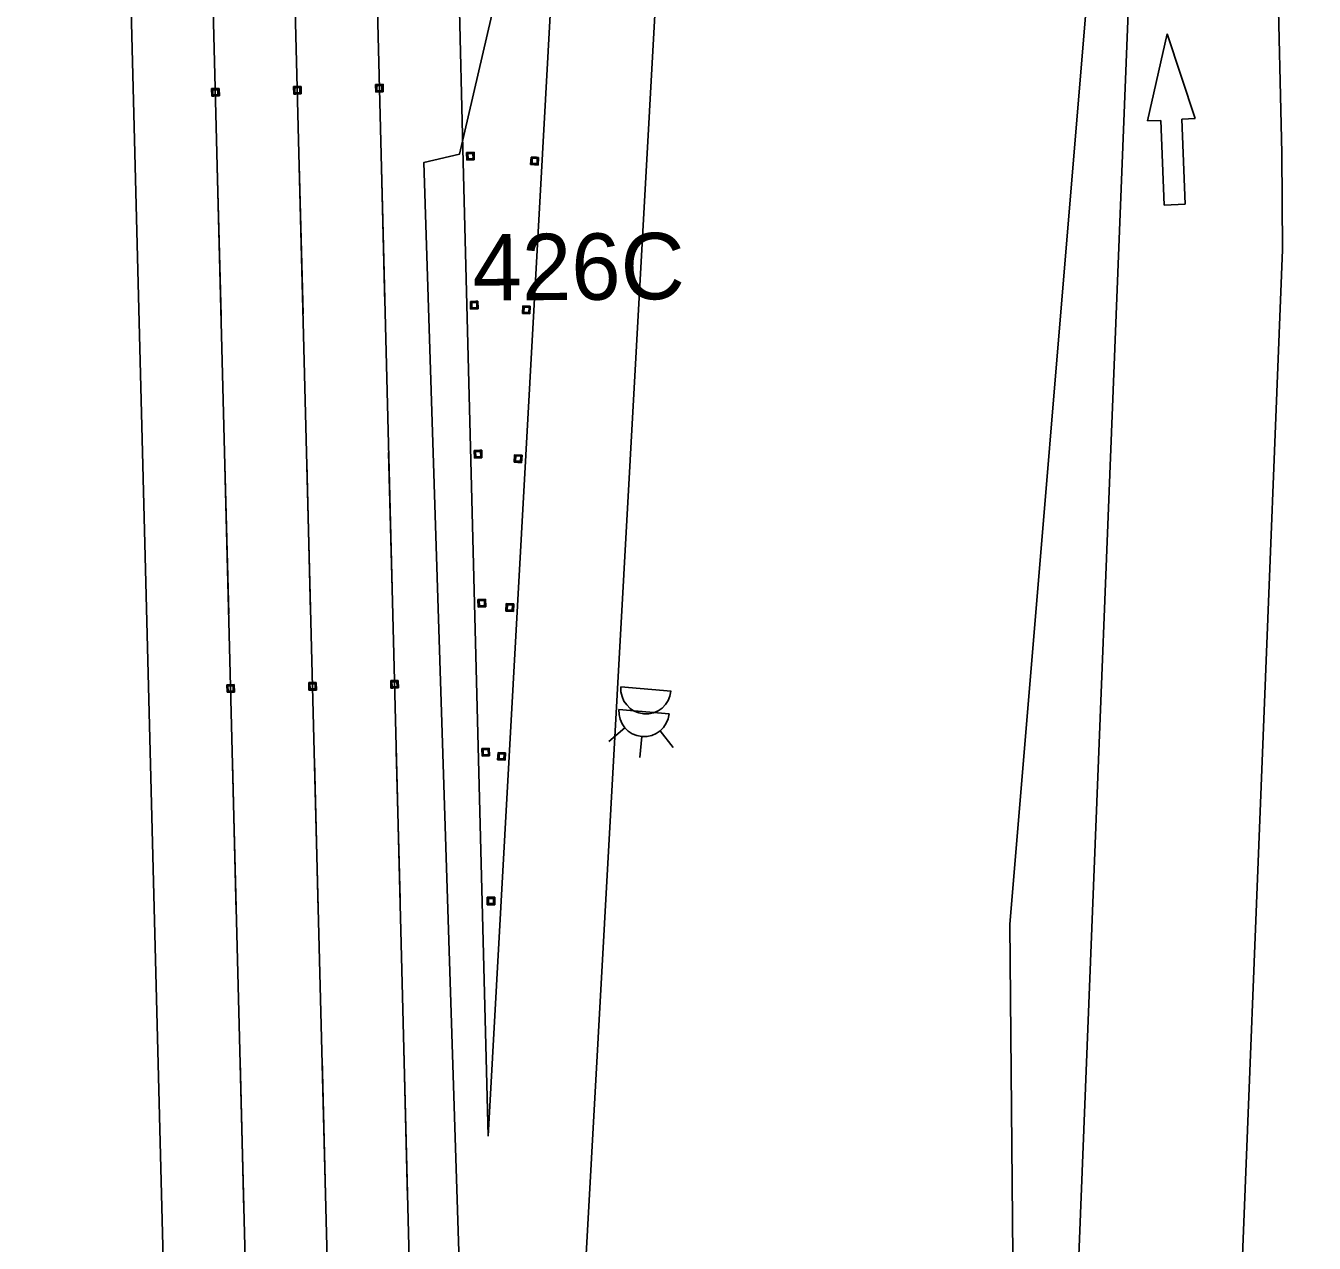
# Model space of a CAD drawing. Extents: x 2471014 to 2497726, y 6959577 to 6980268.
# Drawn here: x 2488544.1 to 2488716.9, y 6961658.6 to 6961822 of the extents above; entities that cross this region are included whole.
import ezdxf

# ---------------------------------------------------------------- set-up
doc = ezdxf.new("R2010")
doc.units = 0
for name, color, linetype in [('13', 7, 'Continuous'), ('18', 7, 'Continuous'), ('23', 7, 'Continuous'), ('25', 7, 'Continuous'), ('ALIGN_ML_IH35_NB_SB', 7, 'Continuous'), ('C-COMM-IDEN', 7, 'Continuous'), ('PMK_Pav_Mark_Wht_Number', 7, 'Continuous'), ('RDWY_PAVE_XSTREET_FOC', 7, 'Continuous'), ('V7_25', 7, 'Continuous'), ('V7_50', 7, 'Continuous')]:
    doc.layers.add(name, color=color, linetype=linetype)

msp = doc.modelspace()

# ---------------------------------------------------------------- linework, layer by layer
at = {"layer": '13'}
for p, q in [((2488544.08, 6962379.72), (2488575.08, 6961163.02)), ((2488613.41, 6961804.76), (2488630.42, 6962111.35)), ((2488683.27, 6961604.88), (2488692.01, 6961824.92))]:
    msp.add_line(p, q, dxfattribs=at)
at = {"layer": '18'}
for p, q in [((2488588.07, 6962380.84), (2488602.73, 6961805.44)), ((2488616.31, 6961604.28), (2488644.4, 6962110.57)), ((2488707.08, 6961650.46), (2488712.7, 6961791.89))]:
    msp.add_line(p, q, dxfattribs=at)
msp.add_lwpolyline([(2488712.7, 6961791.89), (2488712.61, 6961804.88), (2488712.01, 6961829.87), (2488710.72, 6961854.85), (2488708.49, 6961879.81), (2488698.22, 6961952.71)], dxfattribs=at)
at = {"layer": '23'}
for p, q in [((2488570.03, 6961813.55), (2488569.01, 6961813.53)), ((2488569.04, 6961812.51), (2488569.01, 6961813.53)), ((2488569.01, 6961813.53), (2488569.18, 6961813.36)), ((2488569.19, 6961812.68), (2488569.04, 6961812.51)), ((2488569.18, 6961813.36), (2488569.32, 6961813.36)), ((2488569.87, 6961812.7), (2488569.19, 6961812.68)), ((2488569.32, 6961813.36), (2488569.85, 6961813.38)), ((2488569.85, 6961813.38), (2488570.03, 6961813.55)), ((2488570.05, 6961812.54), (2488569.87, 6961812.7)), ((2488570.03, 6961813.55), (2488570.05, 6961812.54)), ((2488581.02, 6961813.83), (2488580.01, 6961813.81)), ((2488580.04, 6961812.79), (2488580.01, 6961813.81)), ((2488580.01, 6961813.81), (2488580.17, 6961813.64)), ((2488580.19, 6961812.96), (2488580.04, 6961812.79)), ((2488580.04, 6961812.79), (2488580.3, 6961812.8)), ((2488580.17, 6961813.64), (2488580.31, 6961813.64)), ((2488580.87, 6961812.98), (2488580.19, 6961812.96)), ((2488580.3, 6961812.8), (2488581.05, 6961812.82)), ((2488580.31, 6961813.64), (2488580.85, 6961813.66)), ((2488580.85, 6961813.66), (2488581.02, 6961813.83)), ((2488581.05, 6961812.82), (2488580.87, 6961812.98)), ((2488581.02, 6961813.83), (2488581.05, 6961812.82)), ((2488592.02, 6961814.11), (2488591.01, 6961814.09)), ((2488591.03, 6961813.07), (2488591.01, 6961814.09)), ((2488591.01, 6961814.09), (2488591.17, 6961813.92)), ((2488591.19, 6961813.24), (2488591.03, 6961813.07)), ((2488591.03, 6961813.07), (2488591.3, 6961813.08)), ((2488591.17, 6961813.92), (2488591.31, 6961813.92)), ((2488591.86, 6961813.26), (2488591.19, 6961813.24)), ((2488591.3, 6961813.08), (2488592.05, 6961813.1)), ((2488591.31, 6961813.92), (2488591.85, 6961813.94)), ((2488591.85, 6961813.94), (2488592.02, 6961814.11)), ((2488592.05, 6961813.1), (2488591.86, 6961813.26)), ((2488592.02, 6961814.11), (2488592.05, 6961813.1)), ((2488569.04, 6961812.51), (2488569.31, 6961812.52)), ((2488569.31, 6961812.52), (2488570.05, 6961812.54)), ((2488603.97, 6961804.98), (2488603.22, 6961804.96)), ((2488603.25, 6961803.95), (2488603.22, 6961804.96)), ((2488603.22, 6961804.96), (2488603.4, 6961804.8)), ((2488603.42, 6961804.12), (2488603.25, 6961803.95)), ((2488603.4, 6961804.8), (2488604.08, 6961804.82)), ((2488603.96, 6961804.14), (2488603.42, 6961804.12)), ((2488604.1, 6961804.14), (2488603.96, 6961804.14)), ((2488604.24, 6961804.99), (2488603.97, 6961804.98)), ((2488604.08, 6961804.82), (2488604.24, 6961804.99)), ((2488604.26, 6961803.97), (2488604.1, 6961804.14)), ((2488604.24, 6961804.99), (2488604.26, 6961803.97)), ((2488611.81, 6961803.34), (2488611.87, 6961804.35)), ((2488612.61, 6961804.31), (2488611.87, 6961804.35)), ((2488611.87, 6961804.35), (2488612.04, 6961804.18)), ((2488612.04, 6961804.18), (2488612.71, 6961804.14)), ((2488612.88, 6961804.3), (2488612.61, 6961804.31)), ((2488612.71, 6961804.14), (2488612.88, 6961804.3)), ((2488612.88, 6961804.3), (2488612.83, 6961803.28)), ((2488603.25, 6961803.95), (2488604.26, 6961803.97)), ((2488612, 6961803.5), (2488611.81, 6961803.34)), ((2488611.81, 6961803.34), (2488612.83, 6961803.28)), ((2488612.53, 6961803.47), (2488612, 6961803.5)), ((2488612.68, 6961803.46), (2488612.53, 6961803.47)), ((2488612.83, 6961803.28), (2488612.68, 6961803.46)), ((2488604.48, 6961784.99), (2488603.73, 6961784.97)), ((2488603.76, 6961783.96), (2488603.73, 6961784.97)), ((2488603.73, 6961784.97), (2488603.91, 6961784.81)), ((2488603.93, 6961784.13), (2488603.76, 6961783.96)), ((2488603.76, 6961783.96), (2488604.77, 6961783.98)), ((2488603.91, 6961784.81), (2488604.59, 6961784.82)), ((2488604.47, 6961784.14), (2488603.93, 6961784.13)), ((2488604.61, 6961784.15), (2488604.47, 6961784.14)), ((2488604.75, 6961785), (2488604.48, 6961784.99)), ((2488604.59, 6961784.82), (2488604.75, 6961785)), ((2488604.77, 6961783.98), (2488604.61, 6961784.15)), ((2488604.75, 6961785), (2488604.77, 6961783.98)), ((2488610.71, 6961783.37), (2488610.76, 6961784.38)), ((2488610.89, 6961783.53), (2488610.71, 6961783.37)), ((2488610.71, 6961783.37), (2488611.72, 6961783.31)), ((2488611.5, 6961784.34), (2488610.76, 6961784.38)), ((2488610.76, 6961784.38), (2488610.93, 6961784.21)), ((2488611.43, 6961783.5), (2488610.89, 6961783.53)), ((2488610.93, 6961784.21), (2488611.61, 6961784.17)), ((2488611.57, 6961783.49), (2488611.43, 6961783.5)), ((2488611.77, 6961784.33), (2488611.5, 6961784.34)), ((2488611.72, 6961783.31), (2488611.57, 6961783.49)), ((2488611.61, 6961784.17), (2488611.77, 6961784.33)), ((2488611.77, 6961784.33), (2488611.72, 6961783.31)), ((2488604.99, 6961765), (2488604.24, 6961764.98)), ((2488604.27, 6961763.96), (2488604.24, 6961764.98)), ((2488604.24, 6961764.98), (2488604.42, 6961764.81)), ((2488604.42, 6961764.81), (2488605.1, 6961764.83)), ((2488605.26, 6961765), (2488604.99, 6961765)), ((2488605.1, 6961764.83), (2488605.26, 6961765)), ((2488605.26, 6961765), (2488605.28, 6961763.99)), ((2488609.6, 6961763.4), (2488609.65, 6961764.41)), ((2488610.4, 6961764.37), (2488609.65, 6961764.41)), ((2488609.65, 6961764.41), (2488609.82, 6961764.24)), ((2488610.67, 6961764.36), (2488610.4, 6961764.37)), ((2488610.5, 6961764.2), (2488610.67, 6961764.36)), ((2488610.67, 6961764.36), (2488610.61, 6961763.34)), ((2488604.44, 6961764.14), (2488604.27, 6961763.96)), ((2488604.27, 6961763.96), (2488605.28, 6961763.99)), ((2488604.98, 6961764.15), (2488604.44, 6961764.14)), ((2488605.12, 6961764.15), (2488604.98, 6961764.15)), ((2488605.28, 6961763.99), (2488605.12, 6961764.15)), ((2488609.78, 6961763.56), (2488609.6, 6961763.4)), ((2488609.6, 6961763.4), (2488610.61, 6961763.34)), ((2488610.32, 6961763.53), (2488609.78, 6961763.56)), ((2488609.82, 6961764.24), (2488610.5, 6961764.2)), ((2488610.46, 6961763.52), (2488610.32, 6961763.53)), ((2488610.61, 6961763.34), (2488610.46, 6961763.52)), ((2488605.5, 6961745), (2488604.75, 6961744.98)), ((2488604.78, 6961743.97), (2488604.75, 6961744.98)), ((2488604.75, 6961744.98), (2488604.93, 6961744.82)), ((2488604.95, 6961744.14), (2488604.78, 6961743.97)), ((2488604.78, 6961743.97), (2488605.79, 6961743.99)), ((2488604.93, 6961744.82), (2488605.61, 6961744.84)), ((2488605.49, 6961744.16), (2488604.95, 6961744.14)), ((2488605.63, 6961744.16), (2488605.49, 6961744.16)), ((2488605.77, 6961745.01), (2488605.5, 6961745)), ((2488605.61, 6961744.84), (2488605.77, 6961745.01)), ((2488605.79, 6961743.99), (2488605.63, 6961744.16)), ((2488605.77, 6961745.01), (2488605.79, 6961743.99)), ((2488608.49, 6961743.43), (2488608.55, 6961744.44)), ((2488608.68, 6961743.59), (2488608.49, 6961743.43)), ((2488609.29, 6961744.4), (2488608.55, 6961744.44)), ((2488608.55, 6961744.44), (2488608.71, 6961744.27)), ((2488609.21, 6961743.56), (2488608.68, 6961743.59)), ((2488608.71, 6961744.27), (2488609.39, 6961744.23)), ((2488609.35, 6961743.55), (2488609.21, 6961743.56)), ((2488609.56, 6961744.39), (2488609.29, 6961744.4)), ((2488609.5, 6961743.37), (2488609.35, 6961743.55)), ((2488609.39, 6961744.23), (2488609.56, 6961744.39)), ((2488609.56, 6961744.39), (2488609.5, 6961743.37)), ((2488608.49, 6961743.43), (2488609.5, 6961743.37)), ((2488572.06, 6961733.58), (2488571.05, 6961733.55)), ((2488571.08, 6961732.54), (2488571.05, 6961733.55)), ((2488571.05, 6961733.55), (2488571.21, 6961733.39)), ((2488571.21, 6961733.39), (2488571.36, 6961733.39)), ((2488571.36, 6961733.39), (2488571.89, 6961733.4)), ((2488571.89, 6961733.4), (2488572.06, 6961733.58)), ((2488572.06, 6961733.58), (2488572.09, 6961732.56)), ((2488583.06, 6961733.86), (2488582.05, 6961733.83)), ((2488582.07, 6961732.82), (2488582.05, 6961733.83)), ((2488582.05, 6961733.83), (2488582.21, 6961733.67)), ((2488582.21, 6961733.67), (2488582.35, 6961733.67)), ((2488582.35, 6961733.67), (2488582.89, 6961733.68)), ((2488582.89, 6961733.68), (2488583.06, 6961733.86)), ((2488583.06, 6961733.86), (2488583.09, 6961732.84)), ((2488594.06, 6961734.14), (2488593.04, 6961734.11)), ((2488593.07, 6961733.1), (2488593.04, 6961734.11)), ((2488593.04, 6961734.11), (2488593.21, 6961733.95)), ((2488593.22, 6961733.27), (2488593.07, 6961733.1)), ((2488593.21, 6961733.95), (2488593.35, 6961733.95)), ((2488593.9, 6961733.29), (2488593.22, 6961733.27)), ((2488593.35, 6961733.95), (2488593.88, 6961733.96)), ((2488593.88, 6961733.96), (2488594.06, 6961734.14)), ((2488594.08, 6961733.12), (2488593.9, 6961733.29)), ((2488594.06, 6961734.14), (2488594.08, 6961733.12)), ((2488571.23, 6961732.71), (2488571.08, 6961732.54)), ((2488571.08, 6961732.54), (2488571.35, 6961732.54)), ((2488571.91, 6961732.73), (2488571.23, 6961732.71)), ((2488571.35, 6961732.54), (2488572.09, 6961732.56)), ((2488572.09, 6961732.56), (2488571.91, 6961732.73)), ((2488582.23, 6961732.99), (2488582.07, 6961732.82)), ((2488582.07, 6961732.82), (2488582.34, 6961732.82)), ((2488582.91, 6961733.01), (2488582.23, 6961732.99)), ((2488582.34, 6961732.82), (2488583.09, 6961732.84)), ((2488583.09, 6961732.84), (2488582.91, 6961733.01)), ((2488593.07, 6961733.1), (2488593.34, 6961733.1)), ((2488593.34, 6961733.1), (2488594.08, 6961733.12)), ((2488606.01, 6961725.01), (2488605.26, 6961724.99)), ((2488605.29, 6961723.98), (2488605.26, 6961724.99)), ((2488605.26, 6961724.99), (2488605.44, 6961724.83)), ((2488605.44, 6961724.83), (2488606.12, 6961724.84)), ((2488606.27, 6961725.02), (2488606.01, 6961725.01)), ((2488606.12, 6961724.84), (2488606.27, 6961725.02)), ((2488606.27, 6961725.02), (2488606.3, 6961724)), ((2488605.46, 6961724.15), (2488605.29, 6961723.98)), ((2488605.29, 6961723.98), (2488606.3, 6961724)), ((2488606, 6961724.16), (2488605.46, 6961724.15)), ((2488606.14, 6961724.17), (2488606, 6961724.16)), ((2488606.3, 6961724), (2488606.14, 6961724.17)), ((2488607.38, 6961723.46), (2488607.44, 6961724.48)), ((2488607.57, 6961723.62), (2488607.38, 6961723.46)), ((2488607.38, 6961723.46), (2488608.39, 6961723.41)), ((2488608.18, 6961724.43), (2488607.44, 6961724.48)), ((2488607.44, 6961724.48), (2488607.61, 6961724.3)), ((2488608.1, 6961723.59), (2488607.57, 6961723.62)), ((2488607.61, 6961724.3), (2488608.28, 6961724.26)), ((2488608.24, 6961723.58), (2488608.1, 6961723.59)), ((2488608.45, 6961724.42), (2488608.18, 6961724.43)), ((2488608.39, 6961723.41), (2488608.24, 6961723.58)), ((2488608.28, 6961724.26), (2488608.45, 6961724.42)), ((2488608.45, 6961724.42), (2488608.39, 6961723.41)), ((2488606.72, 6961705.05), (2488605.98, 6961705.03)), ((2488606, 6961704.01), (2488605.98, 6961705.03)), ((2488605.98, 6961705.03), (2488606.16, 6961704.86)), ((2488606.18, 6961704.19), (2488606, 6961704.01)), ((2488606, 6961704.01), (2488607.02, 6961704.04)), ((2488606.16, 6961704.86), (2488606.84, 6961704.88)), ((2488606.71, 6961704.2), (2488606.18, 6961704.19)), ((2488606.85, 6961704.2), (2488606.71, 6961704.2)), ((2488606.99, 6961705.05), (2488606.72, 6961705.05)), ((2488606.84, 6961704.88), (2488606.99, 6961705.05)), ((2488607.02, 6961704.04), (2488606.85, 6961704.2)), ((2488606.99, 6961705.05), (2488607.02, 6961704.04))]:
    msp.add_line(p, q, dxfattribs=at)
for points in [[(2488569.19, 6961812.68), (2488569.18, 6961813.36), (2488569.85, 6961813.38), (2488569.87, 6961812.7)], [(2488580.19, 6961812.96), (2488580.17, 6961813.64), (2488580.85, 6961813.66), (2488580.87, 6961812.98)], [(2488591.19, 6961813.24), (2488591.17, 6961813.92), (2488591.85, 6961813.94), (2488591.86, 6961813.26)], [(2488604.08, 6961804.82), (2488604.1, 6961804.14), (2488603.42, 6961804.12), (2488603.4, 6961804.8)], [(2488612.71, 6961804.14), (2488612.68, 6961803.46), (2488612, 6961803.5), (2488612.04, 6961804.18)], [(2488604.59, 6961784.82), (2488604.61, 6961784.15), (2488603.93, 6961784.13), (2488603.91, 6961784.81)], [(2488611.61, 6961784.17), (2488611.57, 6961783.49), (2488610.89, 6961783.53), (2488610.93, 6961784.21)], [(2488605.1, 6961764.83), (2488605.12, 6961764.15), (2488604.44, 6961764.14), (2488604.42, 6961764.81)], [(2488610.5, 6961764.2), (2488610.46, 6961763.52), (2488609.78, 6961763.56), (2488609.82, 6961764.24)], [(2488605.61, 6961744.84), (2488605.63, 6961744.16), (2488604.95, 6961744.14), (2488604.93, 6961744.82)], [(2488609.39, 6961744.23), (2488609.35, 6961743.55), (2488608.68, 6961743.59), (2488608.71, 6961744.27)], [(2488571.23, 6961732.71), (2488571.21, 6961733.39), (2488571.89, 6961733.4), (2488571.91, 6961732.73)], [(2488582.23, 6961732.99), (2488582.21, 6961733.67), (2488582.89, 6961733.68), (2488582.91, 6961733.01)], [(2488593.22, 6961733.27), (2488593.21, 6961733.95), (2488593.88, 6961733.96), (2488593.9, 6961733.29)], [(2488606.12, 6961724.84), (2488606.14, 6961724.17), (2488605.46, 6961724.15), (2488605.44, 6961724.83)], [(2488608.28, 6961724.26), (2488608.24, 6961723.58), (2488607.57, 6961723.62), (2488607.61, 6961724.3)], [(2488606.84, 6961704.88), (2488606.85, 6961704.2), (2488606.18, 6961704.19), (2488606.16, 6961704.86)]]:
    msp.add_lwpolyline(points, close=True, dxfattribs=at)
at = {"layer": '25'}
for p, q in [((2488602.73, 6961805.44), (2488606.1, 6961673)), ((2488606.1, 6961673), (2488613.41, 6961804.76))]:
    msp.add_line(p, q, dxfattribs=at)
at = {"layer": 'ALIGN_ML_IH35_NB_SB'}
for p, q in [((2488694.55, 6961809.2), (2488697.2, 6961820.89)), ((2488697.2, 6961820.89), (2488700.96, 6961809.52)), ((2488696.35, 6961809.27), (2488694.55, 6961809.2)), ((2488696.81, 6961797.91), (2488696.35, 6961809.27)), ((2488700.96, 6961809.52), (2488699.17, 6961809.44)), ((2488699.17, 6961809.44), (2488699.63, 6961798.02)), ((2488699.63, 6961798.02), (2488696.81, 6961797.91))]:
    msp.add_line(p, q, dxfattribs=at)
at = {"layer": 'C-COMM-IDEN'}
for p, q in [((2488623.92, 6961733.29), (2488630.65, 6961732.71)), ((2488630.65, 6961732.71), (2488623.92, 6961733.29)), ((2488630.38, 6961729.66), (2488623.66, 6961730.25)), ((2488624.44, 6961727.78), (2488622.31, 6961725.94)), ((2488626.73, 6961726.59), (2488626.48, 6961723.79)), ((2488629.19, 6961727.37), (2488630.92, 6961725.15))]:
    msp.add_line(p, q, dxfattribs=at)
for centre in [(2488627.28, 6961733), (2488627.02, 6961729.95)]:
    msp.add_arc(centre, 3.37, 175.0338, 355.0338, dxfattribs=at)
at = {"layer": 'RDWY_PAVE_XSTREET_FOC'}
for p, q in [((2488591.74, 6961804.7), (2488592.25, 6961784.7)), ((2488570.29, 6961783.04), (2488569.78, 6961803.03)), ((2488581.28, 6961783.32), (2488580.77, 6961803.31)), ((2488592.76, 6961764.71), (2488593.27, 6961744.71)), ((2488571.31, 6961743.05), (2488570.8, 6961763.05)), ((2488582.3, 6961743.33), (2488581.79, 6961763.33)), ((2488593.78, 6961724.72), (2488594.29, 6961704.73)), ((2488572.33, 6961703.07), (2488571.82, 6961723.06)), ((2488583.32, 6961703.35), (2488582.81, 6961723.34)), ((2488573.34, 6961663.08), (2488572.83, 6961683.07)), ((2488584.34, 6961663.36), (2488583.83, 6961683.35)), ((2488594.8, 6961684.73), (2488595.31, 6961664.74))]:
    msp.add_line(p, q, dxfattribs=at)
at = {"layer": 'V7_25'}
for p, q in [((2488555.08, 6962380), (2488586.08, 6961163.33)), ((2488566.07, 6962380.28), (2488597.07, 6961163.64)), ((2488587.67, 6961964.64), (2488608.07, 6961163.94))]:
    msp.add_line(p, q, dxfattribs=at)
at = {"layer": 'V7_50'}
for points in [[(2488678.56, 6961429.45), (2488676.12, 6961701.4), (2488686.81, 6961829.79), (2488681.81, 6961899.73), (2488663.06, 6962024.65), (2488658.12, 6962106.11), (2488660.52, 6962142.63), (2488663.59, 6962148.19), (2488665.59, 6962148.17), (2488667.89, 6962147.73), (2488668.9, 6962274.3), (2488671.26, 6962295.73), (2488674.47, 6962319.21), (2488677.73, 6962343.9), (2488686.19, 6962346.8), (2488706.86, 6962347.54), (2488716.94, 6962346.72), (2488715.38, 6962456.34)], [(2488606.41, 6962447.22), (2488605.3, 6962104.13), (2488608.48, 6961831.56), (2488602.28, 6961804.75), (2488597.48, 6961803.6), (2488609.69, 6961423.76)]]:
    msp.add_lwpolyline(points, dxfattribs=at)

# ---------------------------------------------------------------- texts
at = {"layer": 'PMK_Pav_Mark_Wht_Number'}
msp.add_text('426C', height=8.9, rotation=0.4608, dxfattribs=at).set_placement((2488604.06, 6961785.07))

doc.saveas('drawing.dxf')
